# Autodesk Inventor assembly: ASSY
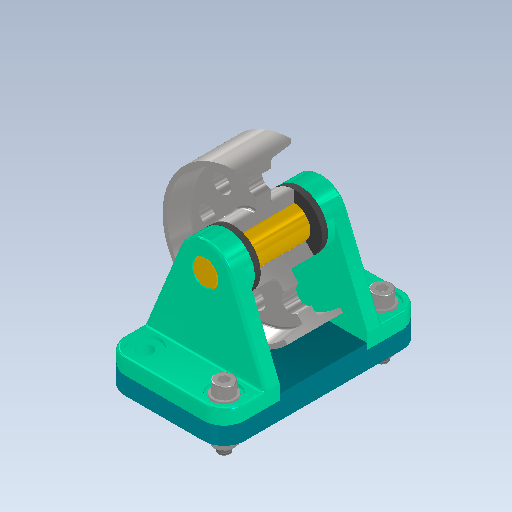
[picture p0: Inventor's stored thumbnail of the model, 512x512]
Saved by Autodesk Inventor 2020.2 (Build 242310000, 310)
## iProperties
Created: 2019-12
Part Number: ASSY
Document SubType Name: Assembly
Designer: Synergysoft Dell02
Author: Synergysoft Dell02
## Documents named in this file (9)
- C:\Users\Synergysoft Dell02\Desktop\INV-01 Intro to Modeling_2020\Wheel Assem Final V1\ASSY.iam
- C:\Users\Synergysoft Dell02\Desktop\INV-01 Intro to Modeling_2020\Wheel Assem Final V1\Plate V1.ipt
- C:\Users\Synergysoft Dell02\Desktop\INV-01 Intro to Modeling_2020\Wheel Assem Final V1\Shaft V1.ipt
- C:\Users\Synergysoft Dell02\Desktop\INV-01 Intro to Modeling_2020\Wheel Assem Final V1\Support Wheel V1.ipt
- C:\Users\Synergysoft Dell02\Desktop\INV-01 Intro to Modeling_2020\Wheel Assem Final V1\Wheel V1.ipt
- C:\Users\Synergysoft Dell02\Desktop\INV-01 Intro to Modeling_2020\Wheel Assem Final V1\ASSY\Design Accelerator\Bolted Connection1.iam
- C:\Users\Synergysoft Dell02\Desktop\INV-01 Intro to Modeling_2020\Wheel Assem Final V1\ASSY\Design Accelerator\Bolted Connection2.iam
- C:\Users\Synergysoft Dell02\Desktop\INV-01 Intro to Modeling_2020\Wheel Assem Final V1\ASSY\Design Accelerator\Bolted Connection3.iam
- C:\Users\Synergysoft Dell02\Desktop\INV-01 Intro to Modeling_2020\Wheel Assem Final V1\Seal_1.ipt
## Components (10 placed, 6 different names)
1. Plate V1:1 — Mate:1, Mate:2, Flush:1, Insert:1, Insert:2, Angle:1
2. Shaft V1:1 — Mate:3, Flush:2, Mate:4, Mate:5
3. Support Wheel V1:1 — Insert:1, Insert:2, Mate:6, Mate:7, Mate:8, Mate:9, Insert:3
4. Wheel V1:1 — Mate:4, Mate:5, Angle:1
5. Support Wheel V1:2 — Mate:1, Mate:2, Flush:1, Mate:3, Flush:2, Mate:10, Mate:11, Flush:4
6. Bolted Connection:1 [sub-assembly] — Mate:6, Mate:7
7. Bolted Connection:2 [sub-assembly] — Mate:8, Mate:9
8. Bolted Connection:3 [sub-assembly] — Mate:10, Mate:11
9. Seal_1:1 — Flush:4
10. Seal_1:2 — Insert:3
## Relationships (18: Mate 11, Flush 3, Insert 3, Angle 1)
- Mate:1: Plate V1:1 ↔ Support Wheel V1:2
- Mate:2: Plate V1:1 ↔ Support Wheel V1:2
- Flush:1: Plate V1:1 ↔ Support Wheel V1:2
- Insert:1: Plate V1:1 ↔ Support Wheel V1:1
- Insert:2: Plate V1:1 ↔ Support Wheel V1:1
- Mate:3: Shaft V1:1 ↔ Support Wheel V1:2
- Flush:2: Shaft V1:1 ↔ Support Wheel V1:2
- Mate:4: Shaft V1:1 ↔ Wheel V1:1
- Mate:5: Shaft V1:1 ↔ Wheel V1:1
- Angle:1: Plate V1:1 ↔ Wheel V1:1
- Mate:6: Support Wheel V1:1 ↔ Bolted Connection:1
- Mate:7: Support Wheel V1:1 ↔ Bolted Connection:1
- Mate:8: Support Wheel V1:1 ↔ Bolted Connection:2
- Mate:9: Support Wheel V1:1 ↔ Bolted Connection:2
- Mate:10: Support Wheel V1:2 ↔ Bolted Connection:3
- Mate:11: Support Wheel V1:2 ↔ Bolted Connection:3
- Flush:4: Support Wheel V1:2 ↔ Seal_1:1
- Insert:3: Support Wheel V1:1 ↔ Seal_1:2
